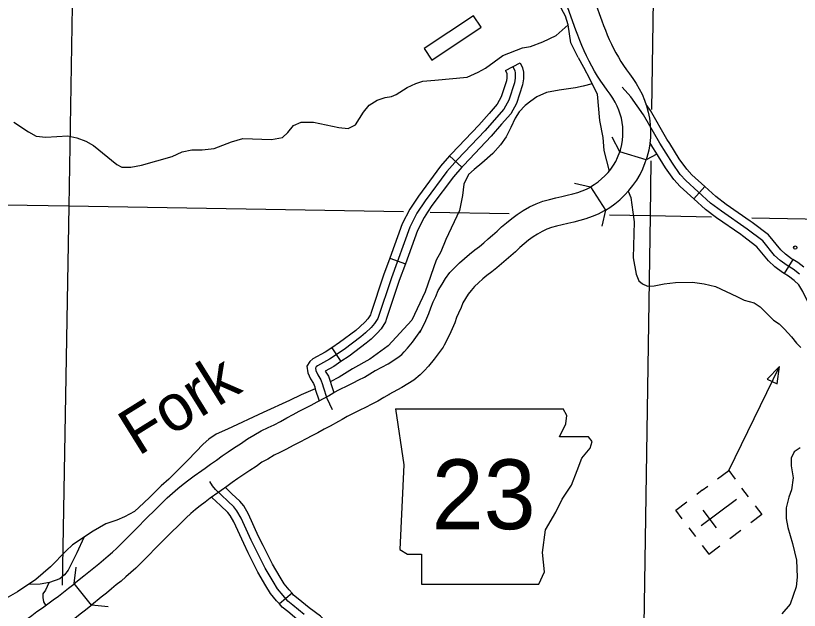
# Model space of a CAD drawing. Extents: x 0 to 3171, y 0 to 2059.
# Drawn here: x 1753.8 to 1872.3, y 964.2 to 1054.2 of the extents above; entities that cross this region are included whole.
import ezdxf

# ---------------------------------------------------------------- set-up
doc = ezdxf.new("R2010")
doc.units = 0
for name, color, linetype in [('Level 10', 7, 'Continuous'), ('Level 21', 7, 'Continuous'), ('Level 35', 7, 'Continuous'), ('Level 37', 7, 'Continuous'), ('Level 45', 7, 'Continuous'), ('Level 5', 7, 'Continuous'), ('Level 57', 7, 'Continuous')]:
    doc.layers.add(name, color=color, linetype=linetype)

msp = doc.modelspace()

# ---------------------------------------------------------------- linework, layer by layer
at = {"layer": 'Level 10'}
for p, q in [((1815.06, 1006.56), (1814.89, 1006.28)), ((1818.58, 1004.34), (1818.4, 1004.06)), ((1808.14, 1000.51), (1808.21, 1000.55)), ((1810.19, 996.88), (1810.25, 996.91)), ((1786.87, 988.86), (1786.88, 988.87)), ((1789.17, 985.38), (1789.18, 985.39))]:
    msp.add_line(p, q, dxfattribs=at)
for points in [[(1841.36, 1056.37), (1842.4, 1053.46), (1842.66, 1052.75), (1842.94, 1052.04), (1843.23, 1051.33), (1843.54, 1050.62), (1843.86, 1049.93), (1844.19, 1049.25), (1844.55, 1048.58), (1844.92, 1047.92), (1845.3, 1047.28), (1845.71, 1046.66), (1846.14, 1046.04), (1846.61, 1045.4), (1847.12, 1044.69), (1847.6, 1043.94), (1848.05, 1043.16), (1848.49, 1042.33), (1848.87, 1041.46), (1849.18, 1040.56), (1849.43, 1039.64), (1849.62, 1038.69), (1849.73, 1037.74), (1849.78, 1036.77), (1849.75, 1035.8), (1849.66, 1034.84), (1849.5, 1033.86), (1849.22, 1032.77), (1849.11, 1032.41), (1845.13, 1033.63)], [(1845.13, 1033.63), (1845.21, 1033.89), (1845.42, 1034.71), (1845.52, 1035.38), (1845.59, 1036.05), (1845.61, 1036.72), (1845.57, 1037.39), (1845.5, 1038.05), (1845.37, 1038.69), (1845.2, 1039.32), (1844.99, 1039.93), (1844.72, 1040.54), (1844.41, 1041.15), (1844.05, 1041.76), (1843.66, 1042.36), (1843.23, 1042.96), (1842.75, 1043.62), (1842.26, 1044.33), (1841.77, 1045.07), (1841.32, 1045.82), (1840.89, 1046.58), (1840.48, 1047.35), (1840.1, 1048.14), (1839.73, 1048.92), (1839.39, 1049.71), (1839.07, 1050.48), (1838.77, 1051.26), (1838.48, 1052.04), (1837.28, 1055.39)], [(1840.72, 1028.31), (1841.27, 1028.66), (1841.85, 1029.07), (1842.38, 1029.51), (1842.88, 1029.98), (1843.35, 1030.48), (1843.78, 1031.02), (1844.17, 1031.58), (1844.51, 1032.16), (1844.8, 1032.76), (1845.13, 1033.63)], [(1842.94, 1024.78), (1843.61, 1025.2), (1844.39, 1025.77), (1845.13, 1026.38), (1845.84, 1027.04), (1846.5, 1027.75), (1847.12, 1028.52), (1847.68, 1029.33), (1848.19, 1030.19), (1848.62, 1031.07), (1848.98, 1031.99), (1849.11, 1032.41)], [(1814.89, 1006.28), (1815.65, 1007.73), (1815.96, 1008.43), (1816.25, 1009.17), (1816.53, 1010.01), (1816.92, 1010.92), (1817.3, 1011.74), (1817.68, 1012.66), (1818.25, 1013.6), (1818.77, 1014.44), (1819.44, 1015.35), (1820.2, 1016.14), (1820.91, 1016.84), (1821.63, 1017.49), (1822.38, 1018.15), (1823.22, 1018.77), (1823.89, 1019.31), (1824.56, 1019.87), (1825.23, 1020.44), (1825.89, 1021.02), (1826.56, 1021.62), (1827.26, 1022.25), (1828, 1022.88), (1828.78, 1023.52), (1829.62, 1024.15), (1830.52, 1024.74), (1831.47, 1025.28), (1832.47, 1025.74), (1833.49, 1026.13), (1834.5, 1026.42), (1835.46, 1026.65), (1836.35, 1026.85), (1837.19, 1027.05), (1838, 1027.25), (1838.76, 1027.48), (1839.46, 1027.72), (1840.1, 1027.98), (1840.69, 1028.29), (1840.72, 1028.31), (1842.94, 1024.78)], [(1842.94, 1024.78), (1842.77, 1024.68), (1841.87, 1024.2), (1840.93, 1023.81), (1840.01, 1023.5), (1839.1, 1023.24), (1838.19, 1023), (1837.29, 1022.79), (1836.39, 1022.59), (1835.56, 1022.39), (1834.8, 1022.17), (1834.08, 1021.9), (1833.38, 1021.57), (1832.69, 1021.18), (1832.01, 1020.74), (1831.34, 1020.24), (1830.68, 1019.69), (1830.01, 1019.12), (1829.34, 1018.51), (1828.65, 1017.9), (1827.95, 1017.28), (1827.24, 1016.68), (1826.53, 1016.09), (1825.78, 1015.48), (1825, 1014.91), (1824.4, 1014.38), (1823.76, 1013.8), (1823.17, 1013.22), (1822.63, 1012.66), (1822.22, 1012.1), (1821.8, 1011.42), (1821.41, 1010.77), (1821.12, 1010.07), (1820.73, 1009.23), (1820.43, 1008.53), (1820.16, 1007.73), (1819.8, 1006.82), (1819.4, 1005.91), (1818.58, 1004.34)], [(1808.21, 1000.55), (1810.08, 1001.55), (1811.55, 1002.49), (1812.16, 1002.97), (1812.53, 1003.34), (1813.03, 1003.9), (1813.76, 1004.82), (1815.06, 1006.56)], [(1818.4, 1004.06), (1817.06, 1002.27), (1816.21, 1001.2), (1815.55, 1000.47), (1814.94, 999.86), (1813.97, 999.09), (1812.19, 997.96), (1810.19, 996.88)], [(1786.88, 988.87), (1787.79, 989.46), (1788.81, 990.17), (1789.81, 990.73), (1790.88, 991.39), (1791.95, 991.9), (1792.86, 992.33), (1793.8, 992.83), (1794.79, 993.36), (1795.72, 993.85), (1796.65, 994.36), (1797.55, 994.81), (1798.44, 995.3), (1799.36, 995.79), (1800.62, 996.46), (1801.08, 996.71), (1801.87, 997.2), (1802.75, 997.64), (1804.01, 998.28), (1804.83, 998.66), (1805.68, 999.11), (1806.5, 999.54), (1807.31, 1000.02), (1808.14, 1000.51)], [(1810.25, 996.91), (1809.43, 996.43), (1808.53, 995.9), (1807.61, 995.42), (1806.69, 994.93), (1805.84, 994.53), (1804.63, 993.92), (1803.91, 993.56), (1803.17, 993.1), (1802.6, 992.79), (1801.32, 992.11), (1800.43, 991.63), (1799.49, 991.12), (1798.58, 990.66), (1797.69, 990.18), (1796.74, 989.67), (1795.76, 989.16), (1794.74, 988.61), (1793.73, 988.13), (1792.87, 987.72), (1791.92, 987.14), (1791.02, 986.64), (1790.12, 986.01), (1789.17, 985.38)], [(1762.64, 968.29), (1764.09, 969.45), (1764.84, 970.07), (1765.59, 970.69), (1766.33, 971.3), (1767.06, 971.9), (1767.76, 972.48), (1768.43, 973.06), (1769.07, 973.66), (1769.72, 974.3), (1770.39, 974.97), (1771.08, 975.68), (1771.79, 976.39), (1772.48, 977.08), (1773.17, 977.77), (1773.86, 978.47), (1774.56, 979.17), (1775.26, 979.87), (1775.97, 980.57), (1776.71, 981.27), (1777.48, 981.99), (1778.28, 982.68), (1779.1, 983.34), (1779.94, 983.98), (1780.77, 984.58), (1781.95, 985.42), (1782.43, 985.75), (1783.26, 986.35), (1784.12, 986.97), (1785.01, 987.6), (1785.93, 988.23), (1786.87, 988.86)], [(1789.18, 985.39), (1788.27, 984.78), (1787.39, 984.18), (1786.53, 983.57), (1785.69, 982.97), (1784.85, 982.36), (1784.37, 982.02), (1783.2, 981.19), (1782.42, 980.63), (1781.68, 980.06), (1780.95, 979.48), (1780.25, 978.88), (1779.56, 978.24), (1778.88, 977.58), (1778.19, 976.9), (1777.5, 976.22), (1776.81, 975.53), (1776.13, 974.84), (1775.43, 974.14), (1774.73, 973.44), (1774.04, 972.75), (1773.36, 972.06), (1772.67, 971.35), (1771.95, 970.64), (1771.21, 969.96), (1770.46, 969.3), (1769.71, 968.68), (1768.98, 968.09), (1768.25, 967.48), (1767.49, 966.86), (1766.72, 966.22), (1765.25, 965.04), (1762.64, 968.29)], [(1755.68, 963.08), (1756.2, 963.46), (1757, 964.05), (1757.81, 964.64), (1758.62, 965.24), (1759.43, 965.83), (1760.23, 966.41), (1761.01, 967), (1761.78, 967.6), (1762.55, 968.21), (1762.64, 968.29)], [(1758.12, 959.7), (1758.66, 960.09), (1759.47, 960.69), (1760.29, 961.29), (1761.09, 961.88), (1761.9, 962.47), (1762.72, 963.08), (1763.54, 963.69), (1764.35, 964.32), (1765.15, 964.96), (1765.25, 965.04)]]:
    msp.add_lwpolyline(points, dxfattribs=at)
at = {"layer": 'Level 21'}
for p, q in [((1811.19, 994.72), (1812.45, 986.27)), ((1837.13, 993.74), (1836.54, 994.71)), ((1836.99, 992.47), (1837.13, 993.74)), ((1836, 990.5), (1836.99, 992.47)), ((1840.37, 990.5), (1836, 990.5)), ((1840.93, 989.79), (1840.37, 990.5)), ((1840.65, 988.8), (1840.93, 989.79)), ((1839.38, 987.25), (1840.65, 988.8)), ((1838.68, 985.42), (1839.38, 987.25)), ((1812.45, 986.27), (1811.89, 973.44)), ((1837.83, 983.16), (1838.68, 985.42)), ((1836.42, 981.05), (1837.83, 983.16)), ((1835.43, 979.08), (1836.42, 981.05)), ((1833.88, 976.4), (1835.43, 979.08)), ((1833.46, 973.01), (1833.88, 976.4)), ((1811.89, 973.44), (1813.02, 972.73)), ((1833.74, 970.05), (1833.46, 973.01)), ((1813.02, 972.73), (1815.13, 972.73)), ((1815.13, 972.73), (1815.13, 968.22)), ((1832.9, 968.22), (1833.74, 970.05)), ((1815.13, 968.22), (1832.9, 968.22))]:
    msp.add_line(p, q, dxfattribs=at)
msp.add_lwpolyline([(1811.19, 994.72), (1836.54, 994.71)], dxfattribs=at)
at = {"layer": 'Level 35'}
for points in [[(1838.83, 1047.9), (1837.72, 1050.12), (1837.33, 1052.81), (1836.91, 1054.12), (1836.3, 1055.25), (1835.77, 1056.4)], [(1808.46, 1041.45), (1809.66, 1041.83), (1810.62, 1042.01), (1811.3, 1042.3), (1812.99, 1043.33), (1814.31, 1043.98), (1815.36, 1044.31), (1817.17, 1044.46), (1822.05, 1044.93), (1823.72, 1045.69), (1824.8, 1046.28), (1827.44, 1048.17), (1830.43, 1049.35), (1831.62, 1049.56), (1833.48, 1050.27), (1835.49, 1051.22), (1837.33, 1052.81)], [(1838.83, 1047.9), (1839.64, 1046.44), (1840.6, 1044.62), (1841.68, 1042.34), (1842.06, 1038.37), (1842.57, 1035.8), (1842.71, 1033.81), (1843.52, 1030.69)], [(1840.94, 1043.9), (1839.58, 1043.54), (1838.43, 1043.29), (1835.97, 1042.97), (1834.04, 1042.61), (1832.56, 1041.95), (1831.67, 1041.29), (1830.82, 1040.65), (1829.89, 1039.69), (1829.29, 1038.73), (1828.67, 1037.29), (1827.96, 1035.89), (1827.11, 1034.66), (1825.94, 1033.35), (1824.29, 1031.88), (1823.11, 1030.96), (1822.27, 1030.17), (1821.53, 1028.74), (1821.34, 1027.03), (1820.9, 1024.76), (1818.83, 1020.33), (1818.07, 1018.49), (1817.37, 1017.21)], [(1753.49, 1038.09), (1755.71, 1036.63), (1756.87, 1035.97), (1758.35, 1035.82), (1761.68, 1036.02), (1763.02, 1035.76), (1764.41, 1035.25), (1765.56, 1034.59), (1769.07, 1031.68), (1769.85, 1031.32), (1771.19, 1031.31), (1772.8, 1031.61), (1777.42, 1032.9), (1778.94, 1033.62), (1780.4, 1033.9), (1782, 1033.92), (1783.8, 1034.1), (1786.43, 1035.13), (1788.13, 1035.65), (1792.46, 1035.49), (1794.11, 1035.77), (1794.95, 1036.53), (1795.77, 1037.58), (1796.94, 1038.13), (1798.81, 1038.1), (1802.64, 1037.29), (1804.05, 1037.14), (1805.18, 1037.72), (1806.39, 1039.64), (1807.21, 1040.69), (1808.46, 1041.45)], [(1846.41, 1027.65), (1846.81, 1026.72), (1847.08, 1024.5), (1847.31, 1023.02), (1847.15, 1017.56), (1847.58, 1015.09), (1847.98, 1014.11), (1848.54, 1013.62), (1849.31, 1013.29), (1850.3, 1013.32), (1851.83, 1013.66), (1853.57, 1013.83), (1856.11, 1013.91), (1857.89, 1013.66), (1859.59, 1013.23), (1862.81, 1011.75), (1863.92, 1011.15), (1865.42, 1010.77), (1866.33, 1010.18), (1867.39, 1009.12), (1868.37, 1008.14), (1869.24, 1007.6), (1870.01, 1006.78), (1871.08, 1005.64), (1871.83, 1004.67), (1872.48, 1004.02)], [(1817.37, 1017.21), (1815.7, 1012.45), (1813.66, 1008.14), (1810.1, 1004.25), (1807.31, 1002.25), (1804.71, 1000.8), (1802.69, 999.53), (1801.33, 998.84)], [(1799.06, 997.75), (1796.97, 996.84), (1795.19, 995.97), (1791.18, 994.17), (1785.8, 991.65), (1784.07, 990.9), (1783, 990.14), (1782.14, 989.37), (1781.03, 988.21), (1779.82, 986.95), (1778.34, 985.52), (1776.93, 984.11), (1775.77, 983.1), (1774.05, 981.38), (1773.14, 980.52), (1771.77, 979.2), (1770.25, 978.39), (1769.08, 977.9), (1767.43, 977.31), (1765.5, 976.2), (1762.39, 974.16), (1761.42, 973.27), (1759.03, 970.82), (1756.83, 968.89), (1754.05, 967.05), (1752.28, 966.05)], [(1872.41, 988.84), (1871.5, 988.21), (1871.03, 987.29), (1871.06, 986.1), (1871.35, 984.31), (1871.1, 982.48), (1870.67, 981.36), (1870.27, 979.77), (1870.28, 978.14), (1870.51, 976.79), (1871.24, 974.38), (1871.84, 971.83), (1871.94, 969.28), (1871.81, 967.81), (1870.91, 965.18), (1869.61, 963.73)], [(1764.06, 975.26), (1763.02, 972.94), (1761.74, 970.33), (1761.18, 969.61), (1760.44, 969.02), (1758.9, 968.43), (1757.5, 968.2), (1755.72, 968.13)], [(1758.79, 968.41), (1758.31, 967.31), (1757.9, 966.73), (1757.86, 966.2), (1757.98, 965.53), (1758.29, 965)]]:
    msp.add_lwpolyline(points, dxfattribs=at)
at = {"layer": 'Level 37'}
for points in [[(1845.13, 1033.63), (1843.96, 1035.84)], [(1850.73, 1033.27), (1849.11, 1032.41)], [(1838.28, 1028.86), (1840.72, 1028.31)], [(1842.94, 1024.78), (1842.39, 1022.35)], [(1762.64, 968.29), (1762.92, 970.77)], [(1767.74, 964.76), (1765.25, 965.04)]]:
    msp.add_lwpolyline(points, dxfattribs=at)
at = {"layer": 'Level 45'}
for p, q in [((1827.82, 1045.93), (1830.05, 1047.07)), ((1819.4, 1032.99), (1821.26, 1031.32)), ((1857.98, 1028.37), (1856.3, 1026.51)), ((1810.35, 1017.54), (1812.7, 1016.69)), ((1871.27, 1017.35), (1870, 1015.2)), ((1801.57, 1003.97), (1802.96, 1001.9)), ((1795.57, 966.83), (1793.67, 965.21))]:
    msp.add_line(p, q, dxfattribs=at)
for points in [[(1828.93, 1046.5), (1829.24, 1045.91), (1829.31, 1045.54), (1829.32, 1044.74), (1829.21, 1044.07), (1828.36, 1041.46), (1827.6, 1040.09), (1824.74, 1036.81), (1820.61, 1032.47), (1818.99, 1030.65), (1815.69, 1026.2), (1814.45, 1024.33), (1813.38, 1022.22), (1810.59, 1014.56), (1808.55, 1008.41), (1808.05, 1007.62), (1807.54, 1007.04), (1806.67, 1006.22), (1805.98, 1005.62), (1803.45, 1003.73), (1801.22, 1002.23), (1799.43, 1001.25), (1799.23, 1001.07), (1799.11, 1000.89), (1799.15, 1000.53), (1799.48, 999.86), (1799.93, 999.13), (1800.19, 998.4), (1800.27, 998.06), (1800.84, 996.37), (1801.61, 994.62)], [(1830.05, 1047.07), (1830.43, 1046.32), (1830.56, 1045.67), (1830.57, 1044.65), (1830.43, 1043.77), (1829.51, 1040.95), (1828.63, 1039.37), (1827.25, 1037.79)], [(1827.82, 1045.93), (1828.05, 1045.49), (1828.06, 1045.41), (1828.07, 1044.83), (1828, 1044.36), (1827.21, 1041.96), (1826.57, 1040.82), (1825.36, 1039.43)], [(1872.31, 1015.11), (1871.35, 1015.85), (1870.41, 1016.4), (1869.37, 1017.16), (1868.54, 1017.95), (1866.73, 1020.15), (1864.41, 1021.92), (1860.48, 1024.64), (1858.86, 1025.87), (1855.12, 1029.27), (1854.26, 1030.21), (1853.07, 1031.88), (1851.19, 1034.91), (1848.71, 1039.21), (1846.8, 1041.92), (1845.5, 1043.39)], [(1852.68, 1034.88), (1852.26, 1035.55), (1849.76, 1039.88), (1849.12, 1040.8)], [(1825.36, 1039.43), (1823.82, 1037.65), (1819.69, 1033.32), (1819.4, 1032.99)], [(1827.25, 1037.79), (1825.67, 1035.97), (1821.53, 1031.62), (1821.26, 1031.32)], [(1850.56, 1033.56), (1850.11, 1034.27), (1849.69, 1035.01)], [(1857.98, 1028.37), (1856.01, 1030.15), (1855.24, 1031), (1854.11, 1032.57), (1852.68, 1034.88)], [(1856.3, 1026.51), (1854.24, 1028.38), (1853.29, 1029.42), (1852.03, 1031.19), (1850.56, 1033.56)], [(1819.4, 1032.99), (1818.02, 1031.44), (1814.67, 1026.92), (1813.96, 1025.85)], [(1821.26, 1031.32), (1819.96, 1029.86), (1816.72, 1025.48), (1816.04, 1024.47)], [(1864.84, 1023.14), (1861.21, 1025.65), (1859.66, 1026.84), (1857.98, 1028.37)], [(1863.42, 1021.09), (1859.74, 1023.63), (1858.06, 1024.91), (1856.3, 1026.51)], [(1813.96, 1025.85), (1813.37, 1024.96), (1812.23, 1022.72), (1810.35, 1017.54)], [(1816.04, 1024.47), (1815.53, 1023.7), (1814.53, 1021.72), (1812.7, 1016.69)], [(1871.27, 1017.35), (1871.1, 1017.45), (1870.17, 1018.12), (1869.46, 1018.8), (1867.61, 1021.05), (1865.15, 1022.93), (1864.84, 1023.14)], [(1870, 1015.2), (1869.73, 1015.36), (1868.57, 1016.2), (1867.63, 1017.1), (1865.86, 1019.24), (1863.68, 1020.91), (1863.42, 1021.09)], [(1810.35, 1017.54), (1809.41, 1014.97), (1807.49, 1009.18)], [(1812.7, 1016.69), (1811.77, 1014.15), (1809.86, 1008.39)], [(1872.97, 1016.18), (1872.06, 1016.88), (1871.27, 1017.35)], [(1874.63, 1008.8), (1872.79, 1012.5), (1872.19, 1013.48), (1871.49, 1014.16), (1870.65, 1014.81), (1870, 1015.2)], [(1807.49, 1009.18), (1807.41, 1008.95), (1807.05, 1008.37), (1806.64, 1007.92), (1805.83, 1007.15), (1805.19, 1006.6), (1802.73, 1004.75), (1801.57, 1003.97)], [(1809.86, 1008.39), (1809.69, 1007.87), (1809.06, 1006.86), (1808.44, 1006.17), (1807.51, 1005.29), (1806.76, 1004.65), (1804.18, 1002.71), (1802.96, 1001.9)], [(1801.57, 1003.97), (1800.57, 1003.3), (1798.71, 1002.28), (1798.28, 1001.9), (1797.81, 1001.19), (1797.94, 1000.17), (1798.38, 999.25), (1798.8, 998.58), (1798.99, 998.05), (1799.06, 997.73), (1799.66, 995.95)], [(1802.96, 1001.9), (1801.87, 1001.16), (1800.58, 1000.45), (1801.06, 999.68), (1801.4, 998.75), (1801.47, 998.4), (1801.88, 997.2)], [(1797.39, 963.61), (1795.71, 965.03), (1794.94, 965.64), (1794.2, 966.51), (1793.35, 967.52), (1792.69, 968.61), (1791.49, 970.61), (1789.39, 974.86), (1787.89, 978.2), (1787.24, 979.31), (1786.75, 979.89), (1783.99, 982.52), (1783.55, 983.06), (1783.16, 983.72)], [(1786.47, 981.89), (1785.49, 982.82)], [(1784.74, 980.08), (1783.42, 981.34)], [(1791.18, 974.06), (1790.52, 975.4), (1789, 978.77), (1788.26, 980.04), (1787.66, 980.75), (1786.47, 981.89)], [(1788.94, 972.95), (1788.26, 974.33), (1786.77, 977.63), (1786.21, 978.59), (1785.84, 979.03), (1784.74, 980.08)], [(1795.57, 966.83), (1795.15, 967.32), (1794.37, 968.25), (1793.76, 969.26), (1792.59, 971.21), (1791.18, 974.06)], [(1793.67, 965.21), (1793.24, 965.7), (1792.33, 966.79), (1791.62, 967.97), (1790.39, 970.02), (1788.94, 972.95)], [(1799.81, 959.18), (1800.83, 960.29), (1801.17, 961.19), (1801, 962.13), (1800.6, 962.72), (1799.86, 963.37), (1798.16, 964.6), (1796.5, 966), (1795.81, 966.55), (1795.57, 966.83)], [(1797.97, 960.87), (1798.39, 961.33), (1798.31, 961.41), (1796.62, 962.62), (1794.91, 964.07), (1794.07, 964.74), (1793.67, 965.21)]]:
    msp.add_lwpolyline(points, dxfattribs=at)
at = {"layer": 'Level 5'}
for points in [[(1850.72, 1093.01), (1849.94, 1040.03)], [(1762.75, 1082.94), (1761.8, 1025.38)], [(1849.83, 1032.24), (1849.7, 1023.91)], [(1761.8, 1025.38), (1689.52, 1026.55)], [(1761.8, 1025.38), (1760.82, 968.06)], [(1812.41, 1024.53), (1761.8, 1025.38)], [(1828.38, 1024.26), (1816.46, 1024.46)], [(1849.7, 1023.91), (1843.57, 1024.01)], [(1849.7, 1023.91), (1848.38, 935.93)], [(1858.97, 1023.72), (1849.7, 1023.91)], [(1889.27, 1023.12), (1865.1, 1023.6)]]:
    msp.add_lwpolyline(points, dxfattribs=at)
at = {"layer": 'Level 57'}
for p, q in [((1823, 1054.21), (1815.54, 1049.25)), ((1824.15, 1052.48), (1823, 1054.21)), ((1816.7, 1047.51), (1824.15, 1052.48)), ((1815.54, 1049.25), (1816.7, 1047.51)), ((1857.59, 982.4), (1856.76, 981.79)), ((1857.59, 982.4), (1858.43, 983.04)), ((1864.58, 981.41), (1863.58, 982.74)), ((1857.42, 977.07), (1862.75, 981.07)), ((1859.75, 976.73), (1857.74, 979.41)), ((1860.08, 979.07), (1860.08, 979.07)), ((1860.08, 979.07), (1860.08, 979.07)), ((1855.58, 976.74), (1856.58, 975.41)), ((1861.76, 975.12), (1863.43, 976.37))]:
    msp.add_line(p, q, dxfattribs=at)
for points in [[(1861.59, 985.4), (1869.28, 1001.16)], [(1859.92, 984.15), (1861.59, 985.4), (1862.59, 984.07)], [(1854.58, 978.07), (1853.59, 979.4), (1855.25, 980.65)], [(1865.59, 980.07), (1866.58, 978.73), (1864.92, 977.48)], [(1857.58, 974.07), (1858.58, 972.73), (1860.25, 973.98)]]:
    msp.add_lwpolyline(points, dxfattribs=at)
msp.add_lwpolyline([(1867.4, 999.24), (1868.93, 998.5), (1869.28, 1001.16)], close=True, dxfattribs=at)
msp.add_circle((1871.65, 1019.12), 0.25, dxfattribs=at)

# ---------------------------------------------------------------- texts
at = {"layer": 'Level 21'}
msp.add_text('23', height=10.56, dxfattribs=at).set_placement((1816.69, 976.52))
at = {"layer": 'Level 35'}
msp.add_text('Fork', height=7.04, rotation=31.9013, dxfattribs=at).set_placement((1772.31, 987.5))

doc.saveas('drawing.dxf')
